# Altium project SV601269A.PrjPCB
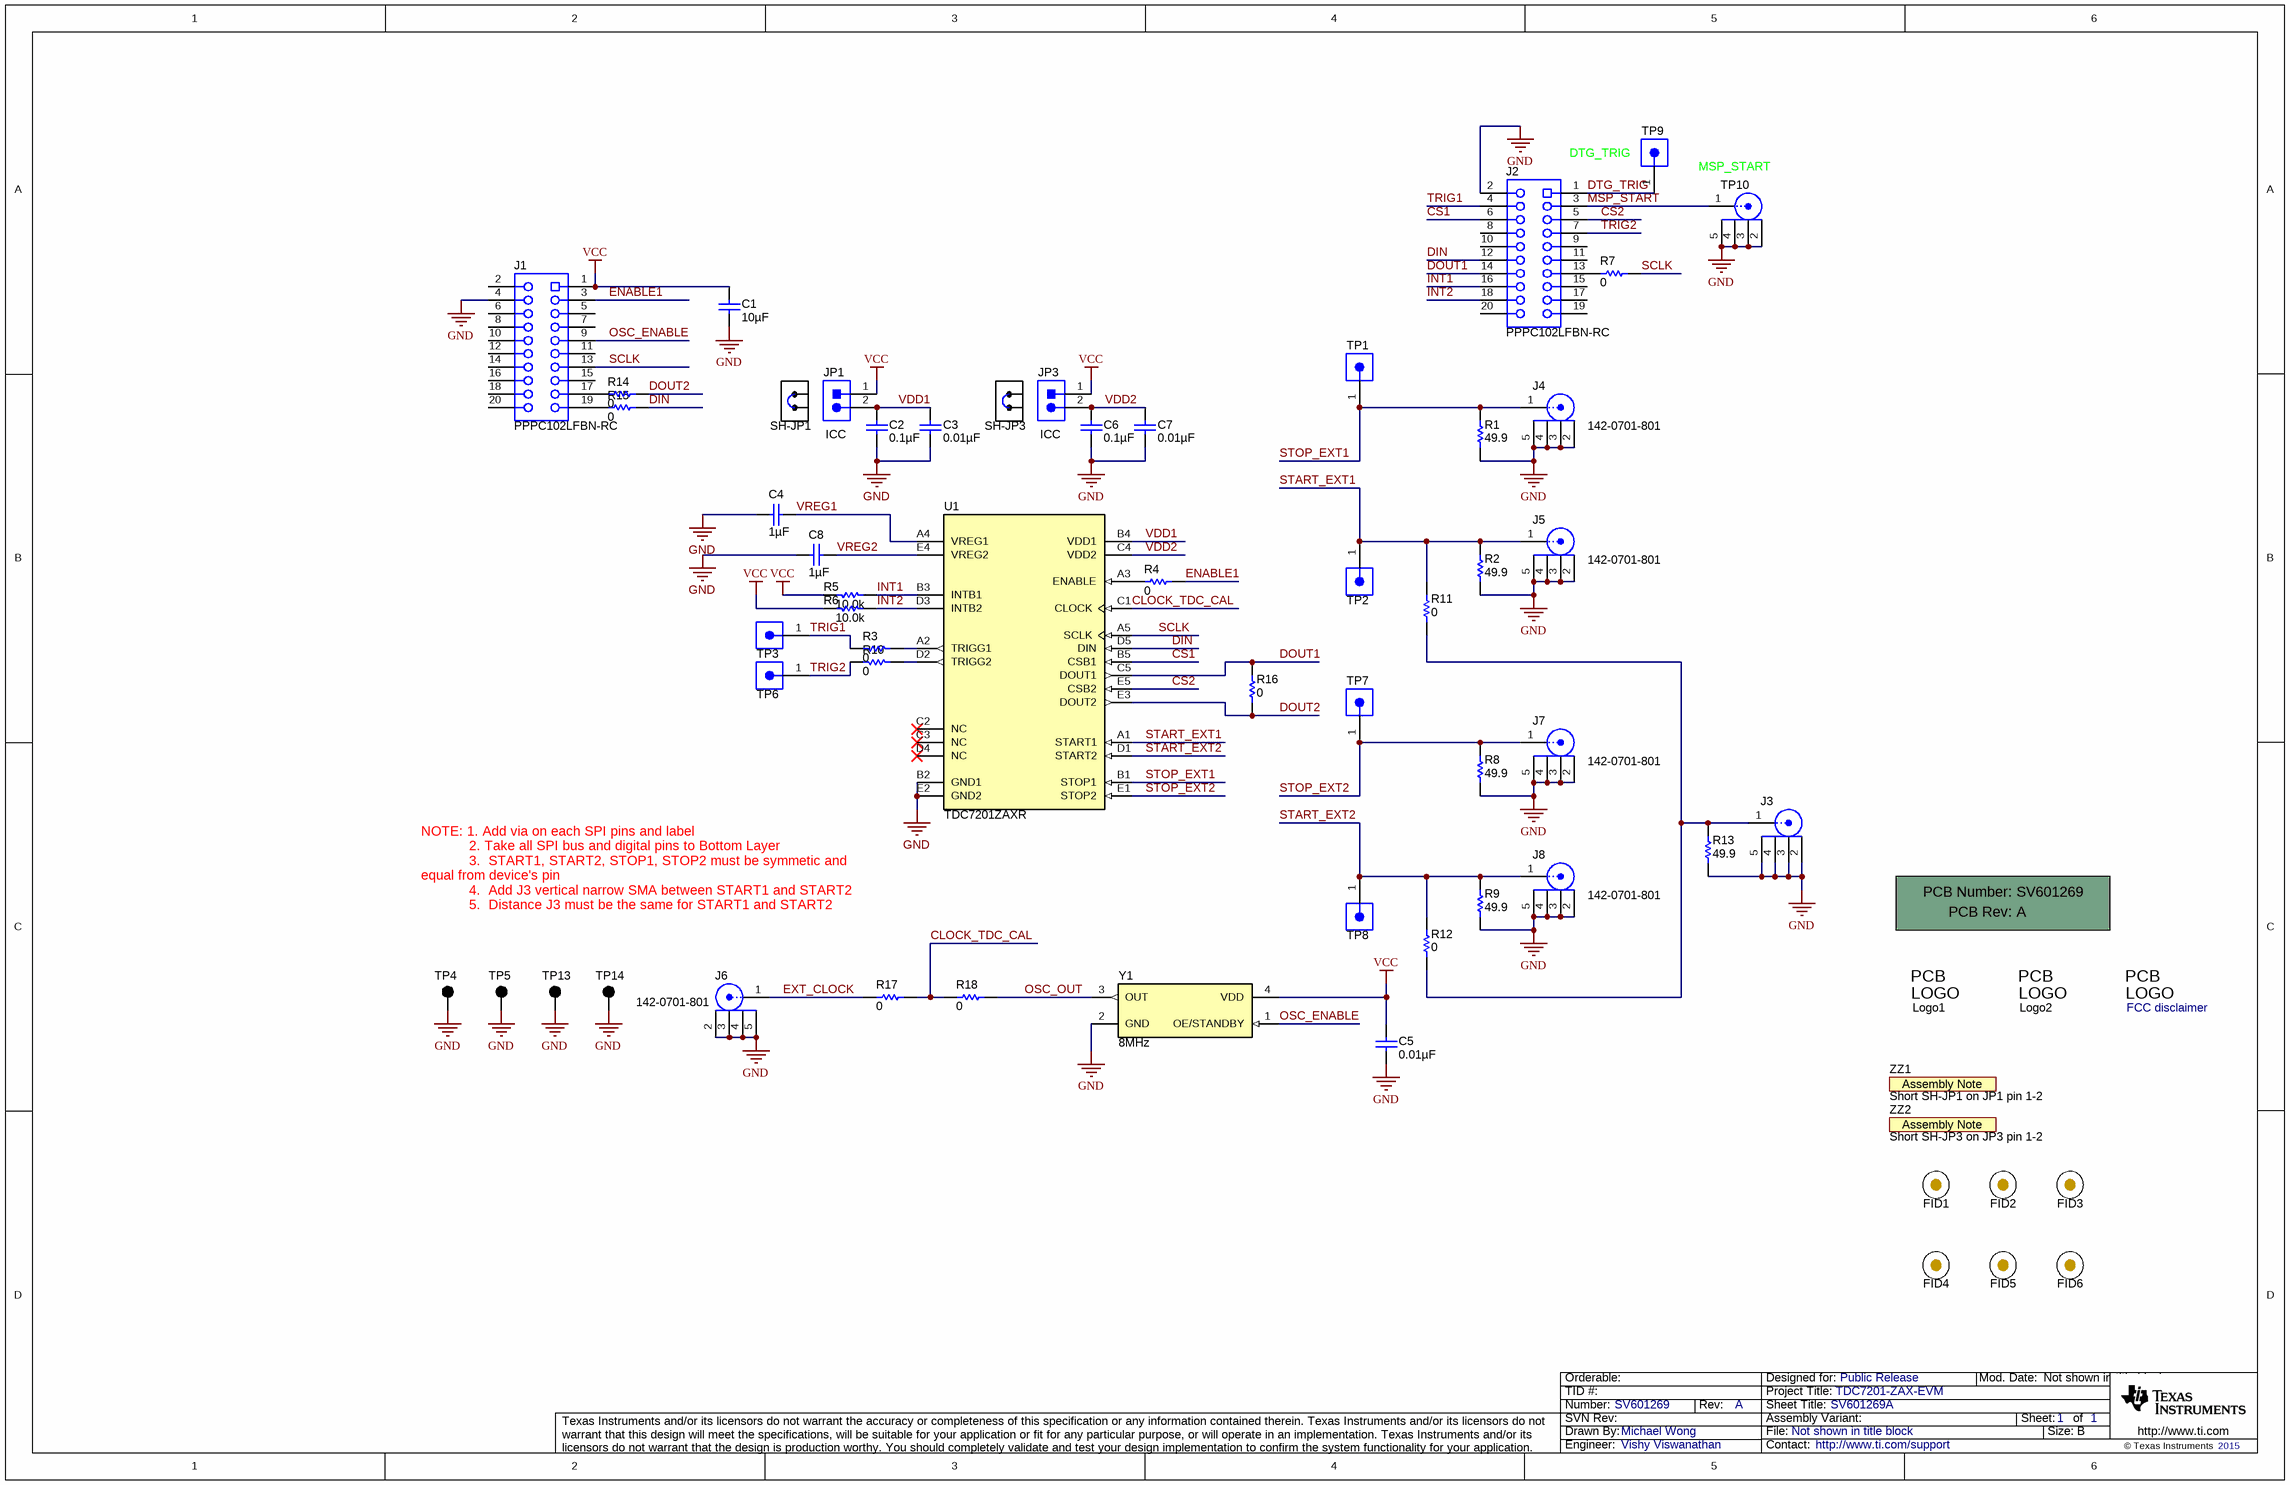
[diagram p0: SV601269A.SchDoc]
CopyrightYear: 2015; PCB_Layout: Krypton Solutions; PCB_Rev: A; PRJ_Customer: Public Release; PRJ_Engineer: Vishy Viswanathan; PRJ_Number: SV601269; PRJ_Title: TDC7201-ZAX-EVM; SCH_Rev: A; TechSupport: http://www.ti.com/support
1 sheet, 64 parts. Net scope: global (net labels, ports and power ports of the same name join across sheets).
Board file: SV601269A.PcbDoc

## Sheet SV601269A.SchDoc: SV601269A
size 431 x 279 mm; Date: Not shown in title block; ApprovedBy: Not shown in title block; CheckedBy: Not shown in title block; Author: Not shown in title block; CompanyName: Not shown in title block; DrawnBy: Michael Wong; Engineer: Michael Wong; Organization: Not shown in title block; Address1: Not shown in title block; Address2: Not shown in title block; Address3: Not shown in title block; Address4: Not shown in title block; DocumentNumber: 1; Revision: Use project parameter SCH_Rev; SheetNumber: 1; SheetTotal: 1; PageSetup: Record=PageOptions¦CenterHorizontal=True¦CenterVertical=True¦PrintScale=1.00¦XCorrection=1.00¦YCorrection=1.00¦PrintKind=0¦BorderSize=5000000¦LeftOffset=0¦BottomOffset=0¦Orientation=2¦PaperLength=1000¦PaperWidth=1000¦Scale=100¦PaperSource=15¦PrintQuality=600¦MediaType=1¦DitherType=10¦PaperKind=Letter¦PrintScaleMode=1

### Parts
!PCB  Printed Circuit Board  (value not drawn)  (mechanical)
C1  ValueDisplayed: 10µF  [0603]  (hidden comment: C0603C106M9PACTU)
C2  ValueDisplayed: 0.1µF  [0603]  (hidden comment: 0603YC104JAT2A)
C3  ValueDisplayed: 0.01µF  [0603]  (hidden comment: 06031C103JAT2A)
C4  ValueDisplayed: 1µF  [0603]  (hidden comment: EMK107B7105KA-T)
C5  ValueDisplayed: 0.01µF  [0603]  (hidden comment: 06031C103JAT2A)
C6  ValueDisplayed: 0.1µF  [0603]  (hidden comment: 0603YC104JAT2A)
C7  ValueDisplayed: 0.01µF  [0603]  (hidden comment: 06031C103JAT2A)
C8  ValueDisplayed: 1µF  [0603]  (hidden comment: EMK107B7105KA-T)
FID1  Fiducial  [Fiducial10-30]  (value not drawn)
FID2  Fiducial  [Fiducial10-30]  (value not drawn)
FID3  Fiducial  [Fiducial10-30]  (value not drawn)
FID4  Fiducial  [Fiducial10-30]  (value not drawn)
FID5  Fiducial  [Fiducial10-30]  (value not drawn)
FID6  Fiducial  [Fiducial10-30]  (value not drawn)
J1  PPPC102LFBN-RC  [Sullins_PPPC102LFBN-RC]
J2  PPPC102LFBN-RC  [Sullins_PPPC102LFBN-RC]
J3  142-0701-201  [Johnson_142-0701-20x]  (value not drawn)
J4  142-0701-801  [JOHNSON_142-0701-801]
J5  142-0701-801  [JOHNSON_142-0701-801]
J6  142-0701-801  [JOHNSON_142-0701-801]
J7  142-0701-801  [JOHNSON_142-0701-801]
J8  142-0701-801  [JOHNSON_142-0701-801]
JP1  TSW-102-07-G-S  [TSW-102-07-G-S]  (value not drawn)
JP3  TSW-102-07-G-S  [TSW-102-07-G-S]  (value not drawn)
Logo1  Texas Instruments  [TI_Stacked_Overlay_Small]  (value not drawn)  (no BOM)
Logo2  Pb-Free Symbol  [Pb-Free_Overlay_Small]  (value not drawn)  (no BOM)
Logo3  FCC disclaimer  [FCC_disclaimer]  (no BOM)
R1  ValueDisplayed: 49.9  [0603]  (hidden comment: CRCW060349R9FKEA)
R2  ValueDisplayed: 49.9  [0603]  (hidden comment: CRCW060349R9FKEA)
R3  ValueDisplayed: 0  [0603]  (hidden comment: CRCW06030000Z0EA)
R4  ValueDisplayed: 0  [0603]  (hidden comment: CRCW06030000Z0EA)
R5  ValueDisplayed: 10.0k  [0603]  (hidden comment: CRCW060310K0FKEA)
R6  ValueDisplayed: 10.0k  [0603]  (hidden comment: CRCW060310K0FKEA)
R7  ValueDisplayed: 0  [0603]  (hidden comment: CRCW06030000Z0EA)
R8  ValueDisplayed: 49.9  [0603]  (hidden comment: CRCW060349R9FKEA)
R9  ValueDisplayed: 49.9  [0603]  (hidden comment: CRCW060349R9FKEA)
R10  ValueDisplayed: 0  [0603]  (hidden comment: CRCW06030000Z0EA)
R11  ValueDisplayed: 0  [0603]  (hidden comment: CRCW06030000Z0EA)
R12  ValueDisplayed: 0  [0603]  (hidden comment: CRCW06030000Z0EA)
R13  ValueDisplayed: 49.9  [0603]  (hidden comment: CRCW060349R9FKEA)
R14  ValueDisplayed: 0  [0603]  (hidden comment: CRCW06030000Z0EA)
R15  ValueDisplayed: 0  [0603]  (hidden comment: CRCW06030000Z0EA)
R16  ValueDisplayed: 0  [0603]  (hidden comment: CRCW06030000Z0EA)
R17  ValueDisplayed: 0  [0603]  (hidden comment: CRCW06030000Z0EA)
R18  ValueDisplayed: 0  [0603]  (hidden comment: CRCW06030000Z0EA)
SH-JP1  969102-0000-DA  [SNT-100-BK-G]  (value not drawn)
SH-JP3  969102-0000-DA  [SNT-100-BK-G]  (value not drawn)
TP1  TSW-101-07-G-S  [TSW-101-07-G-S]  (value not drawn)
TP2  TSW-101-07-G-S  [TSW-101-07-G-S]  (value not drawn)
TP3  TSW-101-07-G-S  [TSW-101-07-G-S]  (value not drawn)
TP4  5011  [Keystone5011]  (value not drawn)
TP5  5011  [Keystone5011]  (value not drawn)
TP6  TSW-101-07-G-S  [TSW-101-07-G-S]  (value not drawn)
TP7  TSW-101-07-G-S  [TSW-101-07-G-S]  (value not drawn)
TP8  TSW-101-07-G-S  [TSW-101-07-G-S]  (value not drawn)
TP9  TSW-101-07-G-S  [TSW-101-07-G-S]  (value not drawn)
TP10  142-0701-201  [Johnson_142-0701-20x]  (value not drawn)
TP13  5011  [Keystone5011]  (value not drawn)
TP14  5011  [Keystone5011]  (value not drawn)
U1  TDC7201ZAXR  [ZAX0025A]
Y1  Frequency: 8MHz  [Abracon_ASFLMB]  (hidden comment: ASFLMB-8.000MHZ-LY-T)
ZZ1  Short SH-JP1 on JP1 pin 1-2  [AssemblyNote]  (no BOM)
ZZ2  Short SH-JP3 on JP3 pin 1-2  [AssemblyNote]  (no BOM)

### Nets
GND: C1.2 C2.2 C3.2 C4.1 C5.2 C6.2 C7.2 C8.1 J1.4 J2.2 J3.2 J3.3 J3.4 J3.5 J4.2 J4.3 J4.4 J4.5 J5.2 J5.3 J5.4 J5.5 J6.2 J6.3 J6.4 J6.5 J7.2 J7.3 J7.4 J7.5 J8.2 J8.3 J8.4 J8.5 R1.1 R2.1 R8.1 R9.1 R13.1 TP4.1 TP5.1 TP10.2 TP10.3 TP10.4 TP10.5 TP13.1 TP14.1 U1.B2(GND1) U1.E2(GND2) Y1.2(GND)
VCC: C1.1 C5.1 J1.1 JP1.1 JP3.1 R5.2 R6.2 Y1.4(VDD)
CLOCK_TDC_CAL: R17.1 R18.2 U1.C1(CLOCK)
CS1: J2.6 U1.B5(CSB1)
CS2: J2.5 U1.E5(CSB2)
DIN: J2.12 R15.2 U1.D5(DIN)
DOUT1: J2.14 R16.1 U1.C5(DOUT1)
DOUT2: R14.2 R16.2 U1.E3(DOUT2)
DTG_TRIG: J2.1 TP9.1
ENABLE1: J1.3 R4.2
EXT_CLOCK: J6.1 R17.2
INT1: J2.16 R5.1 U1.B3(INTB1)
INT2: J2.18 R6.1 U1.D3(INTB2)
MSP_START: J2.3 TP10.1
OSC_ENABLE: J1.9 Y1.1(OE/STANDBY)
OSC_OUT: R18.1 Y1.3(OUT)
SCLK: J1.13 R7.1 U1.A5(SCLK)
START_EXT1: J5.1 R2.2 R11.2 TP2.1 U1.A1(START1)
START_EXT2: J8.1 R9.2 R12.2 TP8.1 U1.D1(START2)
STOP_EXT1: J4.1 R1.2 TP1.1 U1.B1(STOP1)
STOP_EXT2: J7.1 R8.2 TP7.1 U1.E1(STOP2)
TRIG1: J2.4 R3.2 TP3.1
TRIG2: J2.7 R10.2 TP6.1
VDD1: C2.1 C3.1 JP1.2 U1.B4(VDD1)
VDD2: C6.1 C7.1 JP3.2 U1.C4(VDD2)
VREG1: C4.2 U1.A4(VREG1)
VREG2: C8.2 U1.E4(VREG2)
NetJ1_17: J1.17 R14.1
NetJ1_19: J1.19 R15.1
NetJ2_13: J2.13 R7.2
NetJ3_1: J3.1 R11.1 R12.1 R13.2
NetR3_1: R3.1 U1.A2(TRIGG1)
NetR4_1: R4.1 U1.A3(ENABLE)
NetR10_1: R10.1 U1.D2(TRIGG2)

Not connected (* = marked no-connect by the designer): J1 2 5 6 7 8 10 11 12 14 15 16 18 20; J2 8 9 10 11 15 17 19 20; U1 C2(NC)* C3(NC)* D4(NC)*

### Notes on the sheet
- DTG_TRIG
- MSP_START
- ICC
- NOTE: 1. Add via on each SPI pins and label
  2. Take all SPI bus and digital pins to Bottom Layer
  3.  START1, START2, STOP1, STOP2 must be symmetic and equal from device's pin
  4.  Add J3 vertical narrow SMA between START1 and START2
  5.  Distance J3 must be the same for START1 and START2

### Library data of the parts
!PCB = PCB: Manufacturer: Any; PartNumber: SV601269; SymbolCreator: a0412235
C1 = C0603C106M9PACTU: CAP, CERM, 10 µF, 6.3 V, +/- 20%, X5R, 0603; Manufacturer: Kemet; Polarized: N; CompType: Capacitor; Value: 10uF; U/M: EA; Cap_F: 0.00001; Tolerance_%: 20; ESR_ohm: 0.004; Value1: 0.004 ohm; VDC_V: 6.3; Value2: 6.3V; IRMS_A: 8.9; TaMin_C: -55; TaMax_C: 85; AEC Category: Q200
C2 C6 = 0603YC104JAT2A: CAP, CERM, 0.1 µF, 16 V, +/- 5%, X7R, 0603; Manufacturer: AVX; Polarized: N; CompType: Capacitor; Value: 0.1uF; U/M: EA; Cap_F: 0.0000001; Tolerance_%: 5; ESR_ohm: 0.039; Value1: 0.039 ohm; VDC_V: 16; Value2: 16V; TaMin_C: -55; TaMax_C: 125; AEC Category: Q200
C3 C5 C7 = 06031C103JAT2A: CAP, CERM, 0.01 µF, 100 V, +/- 5%, X7R, 0603; Manufacturer: AVX; Polarized: N; CompType: Capacitor; Value: 0.01uF; U/M: EA; Cap_F: 0.00000001; Tolerance_%: 5; ESR_ohm: 0.098; Value1: 0.098 ohm; VDC_V: 100; Value2: 100V; TaMin_C: -55; TaMax_C: 125; AEC Category: Q200
C4 C8 = EMK107B7105KA-T: CAP, CERM, 1 µF, 16 V, +/- 10%, X7R, 0603; Manufacturer: Taiyo Yuden; Polarized: N; CompType: Capacitor; Value: 1uF; U/M: EA; Cap_F: 0.000001; Tolerance_%: 10; Value1: Unknown; VDC_V: 16; Value2: 16V; TaMin_C: -55; TaMax_C: 85; AEC Category: Q200
FID1-FID6 = Fiducial: Fiducial mark.  There is nothing to buy or mount.; SymbolCreator: codlsc
J1 J2 = PPPC102LFBN-RC: Receptacle, 100mil, 10x2, Gold, TH; Manufacturer: Sullins Connector Solutions; SymbolCreator: a0412235
J3 TP10 = 142-0701-201: Connector, TH, SMA; Manufacturer: Emerson Network Power; SymbolCreator: X0208326
J4-J8 = 142-0701-801: Connector, End launch SMA, 50 ohm, SMT; Manufacturer: Johnson; SymbolCreator: X0208326
JP1 JP3 = TSW-102-07-G-S: Header, 100mil, 2x1, Gold, TH; Manufacturer: Samtec; SymbolCreator: a0412235; Pitch_mm: 2.54; Gender: Male; Shrouded: N; Row_Count: 1; Current_A: 6.3; Voltage_V: 550; Cert_CSA: Y
Logo1 = TI_Logo: Texas Instrument Corporate Signature; SymbolCreator: a0412235
Logo2 = Pb-Free: SymbolCreator: a0412235
Logo3 = FCC_disclaimer: SymbolCreator: codlsc
R1 R2 R8 R9 R13 = CRCW060349R9FKEA: RES, 49.9, 1%, 0.1 W, 0603; Manufacturer: Vishay-Dale; CompType: Resistor; Value: 49.9; Value_Code: 49R9; Tolerance_%: 1; Power_W: 0.1; Value2: 0.1W; VDC_V: 75; TempCo: 100 ppm/C; EIA_Code: E96; U/M: EA; AEC Category: Q200
R3 R4 R7 R10-R12 R14-R18 = CRCW06030000Z0EA: RES, 0, 5%, 0.1 W, 0603; Manufacturer: Vishay-Dale; CompType: Resistor; Value: 0; Value_Code: 0000; Tolerance_%: 5; Power_W: 0.1; Value2: 0.1W; VDC_V: 75; TempCo: 200 ppm/C; EIA_Code: E24; U/M: EA; AEC Category: Q200
R5 R6 = CRCW060310K0FKEA: RES, 10.0 k, 1%, 0.1 W, 0603; Manufacturer: Vishay-Dale; CompType: Resistor; Value: 10.0k; Res_ohm: 10000; Value_Code: 10k0; Tolerance_%: 1; Power_W: 0.1; Value2: 0.1W; VDC_V: 75; TempCo: 100 ppm/C; EIA_Code: E96; U/M: EA; AEC Category: Q200
SH-JP1 SH-JP3 = 969102-0000-DA: Shunt, 100mil, Gold plated, Black; Manufacturer: 3M; Alternate Manufacturer: Samtec; Value: 1x2; Note: You can "mate" this to a header by matching the designator.  i.e. use SH-J3 for header J3
TP1-TP3 TP6-TP9 = TSW-101-07-G-S: Header, 100mil, 1pos, Gold, TH; Manufacturer: Samtec; SymbolCreator: a0412235; Pitch_mm: 2.54; Gender: Male; Shrouded: N; Row_Count: 1; Current_A: 6.3; Voltage_V: 550; Cert_CSA: Y
TP4 TP5 TP13 TP14 = 5011: Test Point, Multipurpose, Black, TH; Manufacturer: Keystone; CompType: Test Point Loop; ContactFinish: Silver
U1 = TDC7201ZAXR: Time-to-Digital Converter for Time-of-FlightApplications in LIDAR, Magnetostrictive andFlowMeters, ZAX0025A; Alternate PartNumber: TDC7201ZAXT; Manufacturer: Texas Instruments; SymbolCreator: Altium; CompType: IC; U/M: EA
Y1 = ASFLMB-8.000MHZ-LY-T: OSC, 8MHz, 15pF, SMD; Manufacturer: Abracon Corporation; SymbolCreator: x0208326; CompType: Oscillator; U/M: EA; TaMin_C: -40; TaMax_C: 85; Frequency Stability: ±10ppm
ZZ1 ZZ2 = AssemblyNote: SymbolCreator: codlsc

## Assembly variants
001: not fitted FID1 FID2 FID3 FID4 FID5 FID6 R7 R11 R12 R14 R15 R17 TP1 TP2 TP3 TP6 TP7 TP8 TP10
